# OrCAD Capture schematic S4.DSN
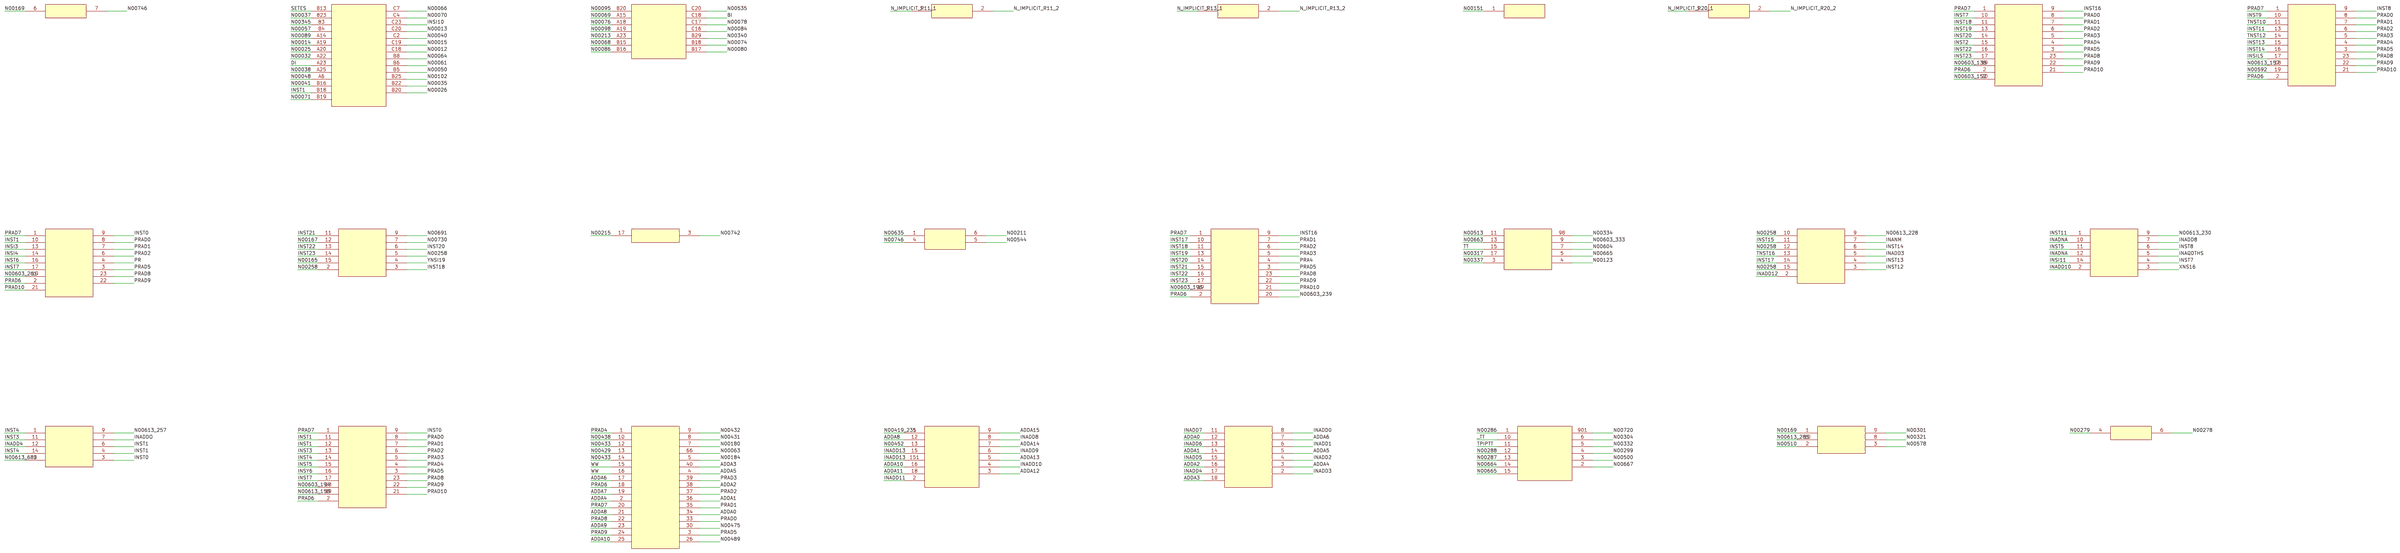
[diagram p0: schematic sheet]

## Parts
J1  CONNECTOR
P1  CONNECTOR
P2  CONNECTOR
R11  1K00
R13  1K00
R18  330R
R20  510R
U1  UNKNOWN
U2  UNKNOWN
U3  UNKNOWN
U13  UNKNOWN
U15  UNKNOWN
U16  74F174
U17  74F32
U19  74F02
U25  74F240
U27  74F174
U28  74F174
U29  74F174
U31  AM291C
U33  74F240
U34  74F240
U38  74F151
U39  74F00
U40  74F103

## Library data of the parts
J1 = OBS_J1
P1 = OBS_P1
P2 = OBS_P2
R11 = OBS_R11
R13 = OBS_R13
R18 = OBS_R18
R20 = OBS_R20
U1 = OBS_U1
U2 = OBS_U2
U3 = OBS_U3
U13 = OBS_U13
U15 = OBS_U15
U16 = OBS_U16
U17 = OBS_U17
U19 = OBS_U19
U25 = OBS_U25
U27 = OBS_U27
U28 = OBS_U28
U29 = OBS_U29
U31 = OBS_U31
U33 = OBS_U33
U34 = OBS_U34
U38 = OBS_U38
U39 = OBS_U39
U40 = OBS_U40

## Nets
_TT: U38.10
ADDA0: U31.34 U34.12
ADDA1: U31.36 U34.14
ADDA2: U31.38 U34.16
ADDA3: U31.40 U34.18
ADDA4: U31.2 U34.3
ADDA5: U31.4 U34.5
ADDA6: U31.17 U34.7
ADDA7: U31.19
ADDA8: U31.21 U33.12
ADDA9: U31.23
ADDA10: U31.25 U33.16
ADDA11: U33.18
ADDA12: U33.3
ADDA13: U33.5
ADDA14: U33.7
ADDA15: U33.9
BI: P2.C18
DI: P1.A23
INADD0: U34.8
INADD1: U34.6
INADD2: U34.4
INADD3: U27.5 U34.2
INADD4: U29.12 U34.17
INADD5: U34.15
INADD6: U34.13
INADD7: U34.11
INADD8: U28.7 U33.8
INADD9: U33.6
INADD10: U28.2 U33.4
INADD11: U33.2
INADD12: U27.2
INADD13: U33.15 U33.151
INADDO: U29.7
INADNA: U28.10 U28.12
INANM: U27.7
INAQDTHS: U28.5
INSI3: U15.13
INSI4: U15.14
INSI10: P1.C23
INSI11: U28.14
INSILS: U13.17
INST0: U3.9 U15.9 U29.3
INST1: P1.B18 U3.11 U3.12 U15.10 U29.4 U29.6
INST2: U1.15
INST3: U3.13 U29.11
INST4: U3.14 U29.1 U29.14
INST5: U3.15 U28.11
INST6: U15.16
INST7: U1.10 U3.17 U15.17 U28.4
INST8: U13.9 U28.6
INST9: U13.10
INST11: U13.13 U28.1
INST12: U27.3
INST13: U13.15 U27.4
INST14: U13.16 U27.6
INST15: U27.11
INST16: U1.9 U2.9
INST17: U2.10 U27.14
INST18: U1.11 U2.11 U16.3
INST19: U1.13 U2.13
INST20: U1.14 U2.14 U16.6
INST21: U2.15 U16.11
INST22: U1.16 U2.16 U16.13
INST23: U1.17 U2.17 U16.14
INSY6: U3.16
N00419_235: U33.1
N00603_138: U1.19
N00603_152: U1.20
N00603_194: U3.18
N00603_196: U2.19
N00603_239: U2.20
N00603_261: U15.19
N00603_333: U25.9
N00613_157: U13.18
N00613_158: U3.19
N00613_228: U27.9
N00613_230: U28.9
N00613_257: U29.9
N00613_285: U39.10
N00613_685: U29.2
N_IMPLICIT_R11_1: R11.1
N_IMPLICIT_R11_2: R11.2
N_IMPLICIT_R13_1: R13.1
N_IMPLICIT_R13_2: R13.2
N_IMPLICIT_R20_1: R20.1
N_IMPLICIT_R20_2: R20.2
PR: U15.4
PRA4: U2.4
PRAD0: U1.8 U3.8 U13.8 U15.8 U31.33
PRAD1: U1.7 U2.7 U3.7 U13.7 U15.7 U31.35
PRAD2: U1.6 U2.6 U3.6 U13.6 U15.6 U31.37
PRAD3: U1.5 U2.5 U3.5 U13.5 U31.39
PRAD4: U1.4 U3.4 U13.4 U31.1
PRAD5: U1.3 U2.3 U3.3 U13.3 U15.3 U31.3
PRAD6: U1.2 U2.2 U3.2 U13.2 U15.2 U31.18
PRAD7: U1.1 U2.1 U3.1 U13.1 U15.1 U31.20
PRAD8: U1.23 U2.23 U3.23 U13.23 U15.23 U31.22
PRAD9: U1.22 U2.22 U3.22 U13.22 U15.22 U31.24
PRAD10: U1.21 U2.21 U3.21 U13.21 U15.21
SETES: P1.813
TNST10: U13.11
TNST12: U13.14
TNST16: U27.13
TPIPTT: U38.11
TT: U25.15
WW: U31.15 U31.16
XNS16: U28.3
YNSI19: U16.4
N00169: J1.6 U39.1
N00258: U16.2 U16.5 U27.10 U27.12 U27.15
N00433: U31.12 U31.14
N00665: U25.5 U38.15
N00746: J1.7 U19.4

Not connected (* = marked no-connect by the designer): P1 83 84 823 A6 A14 A19 A20 A22 A25 B5 B6 B8 B16 B19 B20 B22 B25 C2 C4 C7 C18 C19 C20; P2 820 A15 A18 A19 A23 B15 B16 B17 B18 B29 C16 C17 C20; R18 1; U13 19; U16 7 9 12 15; U17 3 17; U19 1 5 6; U25 3 4 7 11 13 17 98; U31 5 7 8 9 10 13 26 30 66; U33 13; U38 1 2 3 4 5 6 12 13 14 901; U39 2 3 8 9; U40 4 6
